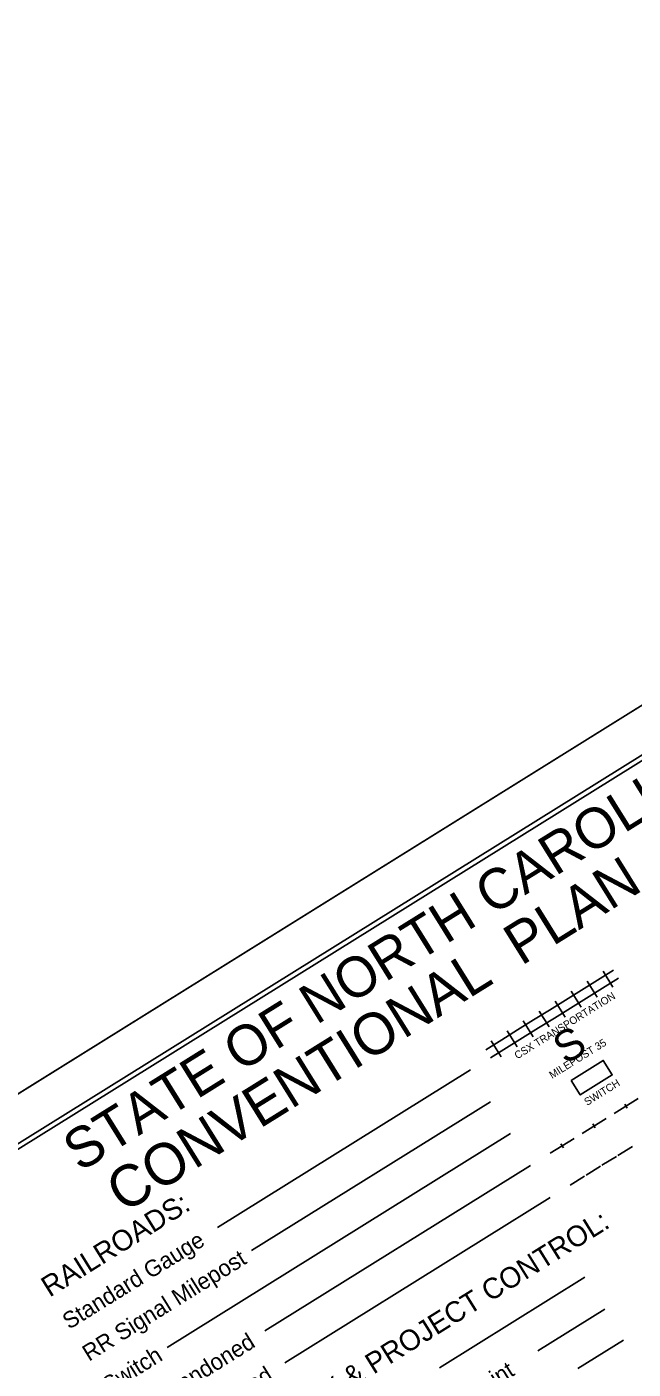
# Model space of a CAD drawing. Extents: x 2046091 to 2048102, y 759061 to 760885.
# Drawn here: x 2046615 to 2046937, y 760172 to 760885 of the extents above; entities that cross this region are included whole.
import ezdxf

# ---------------------------------------------------------------- set-up
doc = ezdxf.new("R2010")
doc.units = 0
for name, color, linetype in [('Sheet Cutting Line CELL', 7, 'Continuous'), ('Sheet Plot Border Inside CELL', 7, 'Continuous'), ('Sheet Plot Border Outside CELL', 7, 'Continuous'), ('Sheet Symbology CELL', 7, 'Continuous')]:
    doc.layers.add(name, color=color, linetype=linetype)

msp = doc.modelspace()

# ---------------------------------------------------------------- linework, layer by layer
at = {"layer": 'Sheet Cutting Line CELL'}
msp.add_line((2047520.01, 760885.29), (2046090.62, 759994.95), dxfattribs=at)
at = {"layer": 'Sheet Plot Border Inside CELL'}
msp.add_lwpolyline([(2046671.37, 759087.19), (2048085.9, 759968.28), (2047528.06, 760863.85), (2046113.53, 759982.76)], close=True, dxfattribs=at)
at = {"layer": 'Sheet Plot Border Outside CELL'}
msp.add_lwpolyline([(2046672.2, 759061.26), (2048101.59, 759951.6), (2047520.01, 760885.29), (2046090.62, 759994.95)], close=True, dxfattribs=at)
at = {"layer": 'Sheet Symbology CELL'}
for p, q in [((2046917.79, 760378.75), (2046926.27, 760384.04)), ((2046926, 760375.03), (2046920.71, 760383.52)), ((2046900.81, 760368.18), (2046909.3, 760373.47)), ((2046909.3, 760373.47), (2046917.79, 760378.75)), ((2046911.94, 760369.22), (2046920.43, 760374.51)), ((2046917.51, 760369.74), (2046912.22, 760378.23)), ((2046920.43, 760374.51), (2046928.92, 760379.8)), ((2046892.32, 760362.89), (2046900.81, 760368.18)), ((2046900.53, 760359.17), (2046895.24, 760367.66)), ((2046903.45, 760363.94), (2046911.94, 760369.22)), ((2046909.02, 760364.46), (2046903.73, 760372.94)), ((2046883.83, 760357.61), (2046892.32, 760362.89)), ((2046892.04, 760353.88), (2046886.76, 760362.37)), ((2046894.97, 760358.65), (2046903.45, 760363.94)), ((2046866.86, 760347.03), (2046875.35, 760352.32)), ((2046875.35, 760352.32), (2046883.83, 760357.61)), ((2046877.99, 760348.07), (2046886.48, 760353.36)), ((2046883.56, 760348.6), (2046878.27, 760357.08)), ((2046886.48, 760353.36), (2046894.97, 760358.65)), ((2046858.37, 760341.74), (2046866.86, 760347.03)), ((2046866.58, 760338.02), (2046861.29, 760346.51)), ((2046869.5, 760342.79), (2046877.99, 760348.07)), ((2046875.07, 760343.31), (2046869.78, 760351.8)), ((2046861.01, 760337.5), (2046869.5, 760342.79)), ((2046850.37, 760331.15), (2046715.91, 760247.4)), ((2046860.94, 760314.17), (2046734, 760235.11)), ((2046926.56, 760307.92), (2046939.29, 760315.85)), ((2046932.27, 760312.95), (2046933.59, 760310.83)), ((2046909.59, 760297.35), (2046922.32, 760305.28)), ((2046915.29, 760302.37), (2046916.61, 760300.25)), ((2046871.52, 760297.2), (2046689.1, 760183.57)), ((2046892.61, 760286.77), (2046905.34, 760294.7)), ((2046898.32, 760291.8), (2046899.64, 760289.68)), ((2046928.65, 760285.66), (2046936.29, 760290.42)), ((2046920.16, 760280.37), (2046927.8, 760285.13)), ((2046882.09, 760280.22), (2046741.05, 760192.37)), ((2046903.18, 760269.8), (2046910.82, 760274.56)), ((2046911.67, 760275.08), (2046919.31, 760279.84)), ((2046892.67, 760263.24), (2046751.63, 760175.39)), ((2046892.67, 760263.24), (2046751.63, 760175.39)), ((2046911.11, 760220.98), (2046833.84, 760172.85)), ((2046921.68, 760204.01), (2046886.1, 760181.84)), ((2046931.57, 760187.54), (2046907.33, 760172.44))]:
    msp.add_line(p, q, dxfattribs=at)
for points in [[(2047518.8, 760855.08), (2046245.59, 760062.02), (2046800.2, 759171.64), (2048073.4, 759964.7)], [(2046903.82, 760325.52), (2046920.8, 760336.09), (2046925.61, 760328.37), (2046908.63, 760317.8)]]:
    msp.add_lwpolyline(points, close=True, dxfattribs=at)

# ---------------------------------------------------------------- texts
for s, height, p in [('STATE OF NORTH CAROLINA, DIVISION OF HIGHWAYS', 21.419, (2046642.81, 760276.5)), ('CONVENTIONAL  PLAN SHEET SYMBOLS', 22.0323, (2046666.04, 760254.59)), ('CSX TRANSPORTATION', 4, (2046875.18, 760336.62)), ('S', 16.5, (2046900.87, 760333.59)), ('MILEPOST 35', 4, (2046893.65, 760326.24)), ('SWITCH', 4, (2046912.24, 760311.9)), ('RAILROADS:', 11, (2046626.7, 760210.03)), ('RIGHT OF WAY & PROJECT CONTROL:', 11, (2046691.98, 760102.57)), ('Standard Gauge', 8.75, (2046637.03, 760192.93)), ('RR Signal Milepost', 8.75, (2046647.6, 760175.96)), ('RR Abandoned', 8.75, (2046668.75, 760142)), ('Switch', 8.75, (2046658.18, 760158.98)), ('RR Dismantled', 8.75, (2046679.32, 760125.03)), ('Primary Horiz and Vert Control Point', 8.75, (2046713.79, 760069.16))]:
    msp.add_text(s, height=height, rotation=31.91803, dxfattribs=at).set_placement(p)

doc.saveas('drawing.dxf')
